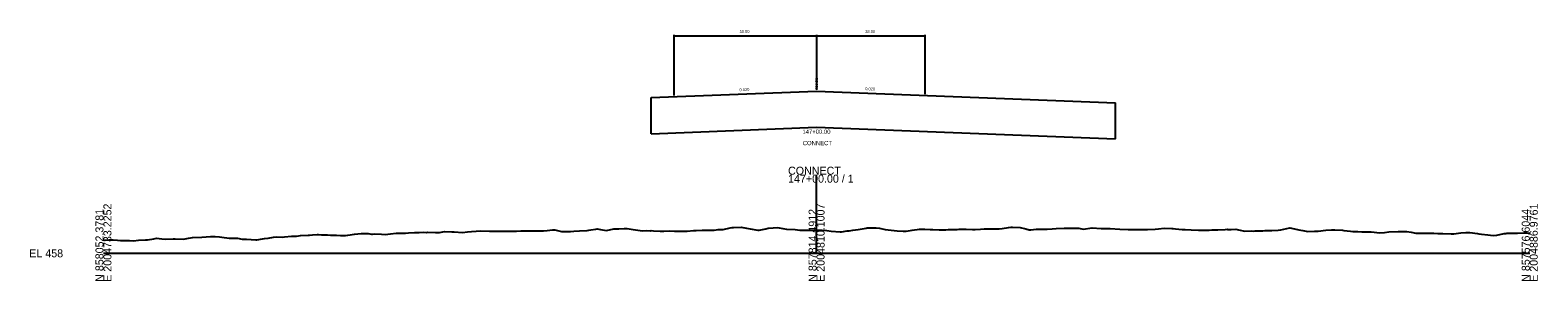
# Model space of a CAD drawing. Extents: x 2004049 to 2067449, y 841632 to 859611.
# Drawn here: x 2062921 to 2063449, y 857704 to 857792 of the extents above; entities that cross this region are included whole.
import ezdxf

# ---------------------------------------------------------------- set-up
doc = ezdxf.new("R2010")
doc.units = 0
for name, color, linetype in [('RD_GPK_XS_Cell', 7, 'Continuous'), ('RD_PD_Bridge', 7, 'Continuous'), ('RD_XS_ExGround', 7, 'Continuous'), ('RD_XS_TX_Elev_EX', 7, 'Continuous'), ('RD_XS_TX_Elev_PR', 7, 'Continuous'), ('RD_XS_TX_Misc', 7, 'Continuous'), ('RD_XS_TX_Slope', 7, 'Continuous'), ('RD_XS_TX_Station', 7, 'Continuous')]:
    doc.layers.add(name, color=color, linetype=linetype)

msp = doc.modelspace()

# ---------------------------------------------------------------- linework, layer by layer
at = {"layer": 'RD_GPK_XS_Cell'}
for p, q in [((2063196.51, 857713.53), (2063196.51, 857741.16)), ((2062946.51, 857713.53), (2063196.51, 857713.53)), ((2063196.51, 857713.53), (2063446.51, 857713.53))]:
    msp.add_line(p, q, dxfattribs=at)
at = {"layer": 'RD_PD_Bridge'}
for p, q in [((2063138.51, 857768.23), (2063196.51, 857770.55)), ((2063138.51, 857755.57), (2063138.51, 857768.23)), ((2063196.51, 857770.55), (2063301.25, 857766.36)), ((2063301.25, 857753.7), (2063301.25, 857766.36)), ((2063138.51, 857755.57), (2063196.51, 857757.89)), ((2063196.51, 857757.89), (2063301.25, 857753.7))]:
    msp.add_line(p, q, dxfattribs=at)
at = {"layer": 'RD_XS_ExGround'}
msp.add_lwpolyline([(2062946.51, 857718.14), (2062948.36, 857718.24), (2062949.37, 857718.28), (2062949.89, 857718.27), (2062951.5, 857718.18), (2062952.53, 857718.06), (2062953.02, 857718.08), (2062955.68, 857717.98), (2062957.04, 857717.95), (2062958.83, 857718.14), (2062961.26, 857718.29), (2062961.99, 857718.31), (2062964.19, 857718.64), (2062965.14, 857718.8), (2062967, 857718.64), (2062968.29, 857718.53), (2062971.01, 857718.57), (2062971.65, 857718.59), (2062974.6, 857718.46), (2062976.31, 857718.83), (2062977.75, 857719.13), (2062980.97, 857719.23), (2062984.06, 857719.49), (2062985.63, 857719.4), (2062987.21, 857719.32), (2062988.02, 857719.19), (2062990.53, 857718.87), (2062993.52, 857718.84), (2062995.17, 857718.54), (2062996.67, 857718.5), (2062999.94, 857718.23), (2063000.29, 857718.29), (2063002.32, 857718.58), (2063002.98, 857718.72), (2063004.27, 857718.85), (2063006.13, 857719.22), (2063007.09, 857719.27), (2063009.29, 857719.24), (2063010.04, 857719.3), (2063012.44, 857719.57), (2063014.24, 857719.61), (2063015.59, 857719.83), (2063018.24, 857719.89), (2063018.75, 857719.93), (2063019.8, 857720.02), (2063021.39, 857720.12), (2063021.9, 857720.19), (2063022.9, 857720.07), (2063025.05, 857720.08), (2063026.15, 857719.94), (2063028.21, 857719.94), (2063029.56, 857719.84), (2063031.36, 857719.77), (2063032.22, 857719.9), (2063034.51, 857720.23), (2063036.88, 857720.51), (2063037.67, 857720.53), (2063038.07, 857720.49), (2063039.32, 857720.45), (2063040.45, 857720.29), (2063040.82, 857720.25), (2063041.54, 857720.34), (2063043.97, 857720.28), (2063045.22, 857720.2), (2063047.13, 857720.36), (2063049.08, 857720.58), (2063050.28, 857720.62), (2063052.37, 857720.62), (2063053.43, 857720.7), (2063055.51, 857720.82), (2063056.59, 857720.87), (2063057.14, 857720.89), (2063058.83, 857720.94), (2063059.74, 857720.9), (2063060.17, 857720.98), (2063062.89, 857720.87), (2063064.29, 857720.79), (2063066.05, 857721.14), (2063068.59, 857721.12), (2063069.49, 857721.04), (2063072.35, 857720.9), (2063074.15, 857721.09), (2063075.51, 857721.15), (2063078.81, 857721.42), (2063081.81, 857721.37), (2063083.47, 857721.28), (2063084.97, 857721.32), (2063088.12, 857721.31), (2063090.5, 857721.28), (2063091.27, 857721.32), (2063092.79, 857721.46), (2063094.43, 857721.38), (2063097.87, 857721.48), (2063100.73, 857721.44), (2063102.1, 857721.58), (2063103.89, 857721.75), (2063104.8, 857721.75), (2063107.04, 857721.23), (2063107.62, 857721.19), (2063110.19, 857721.2), (2063111.42, 857721.28), (2063113.35, 857721.48), (2063116.08, 857721.54), (2063116.72, 857721.65), (2063117.38, 857721.75), (2063119.1, 857722.02), (2063119.65, 857722.08), (2063120.74, 857721.87), (2063122.81, 857721.57), (2063125.4, 857722.1), (2063125.96, 857722.1), (2063127.14, 857722.18), (2063129.11, 857722.24), (2063130.06, 857722.22), (2063132.27, 857721.94), (2063134.72, 857721.56), (2063135.42, 857721.46), (2063136.9, 857721.5), (2063138.16, 857721.46), (2063138.57, 857721.54), (2063139.37, 857721.44), (2063141.73, 857721.3), (2063142.93, 857721.34), (2063144.88, 857721.39), (2063146.65, 857721.37), (2063148.03, 857721.36), (2063150.08, 857721.35), (2063151.19, 857721.36), (2063153.35, 857721.51), (2063154.34, 857721.51), (2063156.41, 857721.61), (2063157.49, 857721.62), (2063158.01, 857721.63), (2063160.65, 857721.65), (2063162, 857721.87), (2063163.8, 857721.91), (2063166.17, 857722.44), (2063166.95, 857722.6), (2063167.33, 857722.6), (2063170.11, 857722.71), (2063171.99, 857722.34), (2063173.26, 857722.18), (2063175.93, 857721.72), (2063176.41, 857721.69), (2063178.68, 857722.16), (2063179.57, 857722.39), (2063181.31, 857722.48), (2063182.72, 857722.62), (2063183.44, 857722.51), (2063185.96, 857722.07), (2063189.03, 857721.89), (2063190.62, 857721.72), (2063192.18, 857721.64), (2063195.44, 857721.63), (2063196.51, 857721.62), (2063198.49, 857721.61), (2063200.13, 857721.53), (2063201.64, 857721.3), (2063204.79, 857721.08), (2063205.2, 857721.12), (2063207.28, 857721.44), (2063207.95, 857721.38), (2063209.26, 857721.65), (2063211.1, 857721.92), (2063213.92, 857722.42), (2063214.25, 857722.5), (2063214.96, 857722.53), (2063217.41, 857722.53), (2063218.58, 857722.36), (2063220.56, 857721.93), (2063221.58, 857721.79), (2063223.71, 857721.51), (2063224.72, 857721.42), (2063226.87, 857721.28), (2063227.89, 857721.32), (2063230.02, 857721.67), (2063232.55, 857721.99), (2063233.17, 857722.02), (2063234.47, 857722), (2063236.33, 857721.95), (2063237.21, 857721.91), (2063239.48, 857721.77), (2063241.87, 857721.84), (2063242.63, 857721.86), (2063244.23, 857721.87), (2063245.79, 857721.86), (2063246.53, 857721.96), (2063248.94, 857721.96), (2063251.19, 857721.92), (2063252.09, 857721.93), (2063253.99, 857722.05), (2063255.25, 857722.11), (2063257.32, 857722.08), (2063258.4, 857722.14), (2063260.51, 857722.08), (2063261.55, 857722.21), (2063263.75, 857722.58), (2063264.71, 857722.73), (2063265.17, 857722.74), (2063267.86, 857722.61), (2063269.82, 857722.14), (2063271.01, 857721.73), (2063271.62, 857721.8), (2063273.51, 857721.97), (2063274.17, 857722.03), (2063274.48, 857722.02), (2063277.32, 857722.06), (2063279.14, 857722.17), (2063280.47, 857722.31), (2063283.26, 857722.4), (2063283.8, 857722.4), (2063286.78, 857722.32), (2063288.46, 857722.34), (2063289.93, 857722.07), (2063293.12, 857722.51), (2063296.24, 857722.26), (2063297.78, 857722.22), (2063299.39, 857722.21), (2063302.78, 857722.03), (2063305.7, 857721.89), (2063307.37, 857721.86), (2063308.85, 857721.85), (2063312.01, 857721.85), (2063312.54, 857721.89), (2063315.16, 857722), (2063316.41, 857722.11), (2063318.31, 857722.32), (2063321.07, 857722.25), (2063321.47, 857722.26), (2063322.29, 857722.17), (2063324.62, 857721.93), (2063325.73, 857721.93), (2063327.77, 857721.81), (2063330.39, 857721.69), (2063330.93, 857721.61), (2063332.05, 857721.66), (2063334.08, 857721.7), (2063335.05, 857721.73), (2063337.23, 857721.8), (2063339.71, 857721.94), (2063340.39, 857721.98), (2063340.73, 857721.94), (2063341.81, 857721.95), (2063343.54, 857721.97), (2063344.37, 857721.8), (2063346.69, 857721.36), (2063349.03, 857721.42), (2063349.85, 857721.37), (2063350.27, 857721.38), (2063351.57, 857721.47), (2063353, 857721.49), (2063353.68, 857721.5), (2063356.15, 857721.53), (2063358.34, 857721.67), (2063359.31, 857721.75), (2063361.33, 857722.22), (2063362.46, 857722.45), (2063363, 857722.35), (2063365.61, 857721.84), (2063366.95, 857721.54), (2063368.77, 857721.23), (2063371.08, 857721.27), (2063371.92, 857721.26), (2063372.32, 857721.32), (2063375.07, 857721.64), (2063376.98, 857721.77), (2063378.23, 857721.8), (2063380.84, 857721.63), (2063381.38, 857721.59), (2063383.63, 857721.32), (2063384.53, 857721.21), (2063386.3, 857721.22), (2063387.69, 857721.11), (2063390.96, 857721.1), (2063393.99, 857720.7), (2063395.55, 857720.84), (2063397.15, 857721.04), (2063400.36, 857721.18), (2063402.7, 857721.17), (2063403.45, 857721.24), (2063404.93, 857720.97), (2063406.61, 857720.61), (2063407.46, 857720.64), (2063409.76, 857720.59), (2063410.11, 857720.59), (2063412.91, 857720.61), (2063414.25, 857720.53), (2063416.07, 857720.52), (2063418.91, 857720.35), (2063419.22, 857720.35), (2063419.87, 857720.43), (2063422.37, 857720.72), (2063424.15, 857720.85), (2063425.53, 857720.83), (2063428.23, 857720.52), (2063428.68, 857720.41), (2063429.63, 857720.3), (2063431.83, 857720.02), (2063433.68, 857719.83), (2063434.99, 857719.9), (2063437.54, 857720.46), (2063438.14, 857720.5), (2063438.45, 857720.62), (2063439.39, 857720.62), (2063440.83, 857720.62), (2063441.29, 857720.63), (2063442.2, 857720.64), (2063444.45, 857720.73), (2063445.59, 857720.72), (2063446.51, 857720.63)], dxfattribs=at)
at = {"layer": 'RD_XS_TX_Misc'}
for p, q in [((2063146.51, 857790.35), (2063146.51, 857768.95)), ((2063146.51, 857789.95), (2063196.51, 857789.95)), ((2063196.51, 857790.35), (2063196.51, 857770.95)), ((2063196.51, 857789.95), (2063234.51, 857789.95)), ((2063234.51, 857790.35), (2063234.51, 857769.43))]:
    msp.add_line(p, q, dxfattribs=at)

# ---------------------------------------------------------------- texts
at = {"layer": 'RD_GPK_XS_Cell'}
for s, p in [('CONNECT', (2063186.51, 857741.16)), ('147+00.00 / 1', (2063186.51, 857738.36)), ('EL 458', (2062920.51, 857712.13))]:
    msp.add_text(s, height=2.8, dxfattribs=at).set_placement(p)
for s, p in [('E 2004733.2252', (2062949.31, 857703.53)), ('E 2004810.1007', (2063199.31, 857703.53)), ('E 2004886.9761', (2063449.31, 857703.53)), ('N 858052.3781', (2062946.51, 857703.53)), ('N 857814.4912', (2063196.51, 857703.53)), ('N 857576.6044', (2063446.51, 857703.53))]:
    msp.add_text(s, height=2.8, rotation=90, dxfattribs=at).set_placement(p)
at = {"layer": 'RD_XS_TX_Elev_EX'}
msp.add_text('462.05', height=0.8, rotation=270, dxfattribs=at).set_placement((2063196.11, 857719.62))
at = {"layer": 'RD_XS_TX_Elev_PR'}
msp.add_text(' 486.51', height=1, rotation=90, dxfattribs=at).set_placement((2063197.01, 857770.55))
at = {"layer": 'RD_XS_TX_Misc'}
for s, p in [('50.00', (2063169.52, 857790.95)), ('38.00', (2063213.56, 857790.95))]:
    msp.add_text(s, height=1, dxfattribs=at).set_placement(p)
at = {"layer": 'RD_XS_TX_Slope'}
for rotation, p in [(2.2906, (2063169.51, 857770.47)), (357.7094, (2063213.53, 857770.87))]:
    msp.add_text('0.020', height=1, rotation=rotation, dxfattribs=at).set_placement(p)
at = {"layer": 'RD_XS_TX_Station'}
for s, p in [('147+00.00', (2063191.54, 857755.52)), ('CONNECT', (2063191.67, 857751.52))]:
    msp.add_text(s, height=1.5, dxfattribs=at).set_placement(p)

doc.saveas('drawing.dxf')
